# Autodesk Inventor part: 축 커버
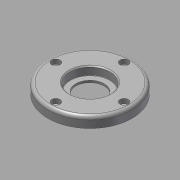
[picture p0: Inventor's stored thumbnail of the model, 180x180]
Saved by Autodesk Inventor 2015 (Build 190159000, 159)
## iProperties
Created: 2015-10
Part Number: 축 커버
Document SubType Name: Modeling
Designer: mdu
Density: 1 g/cm^3
Material: 강철, 연강
Appearance: 강철
Author: mdu
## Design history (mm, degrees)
sketch "스케치1"
  geometry: C1 r 40 at (0, 0) reference; C2 r 26 at (0, 0) reference; 1 further point
  node "참조1"
  node "참조2"
extrude "돌출1" new body sketch "스케치1" distance "d0" = 10; taper "d1" = 0 deg
extrude "돌출2" join sketch "스케치1" distance "d2" = 3; taper "d3" = 0 deg
hole "구멍1" diameter "d6" = 27; stored, may be unused: countersink angle "d10" = 90 deg, drill point angle "d12" = 118 deg; dims "d4" = 10, "d5" = 10, "d7" = 6, "d8" = 38, "d9" = 8, "d11" = 8
sketch "스케치2"
  geometry: C1 r 20 at (0, 0); 1 further point
  constraints: 1 centre point, 1 coincident
  dimensions: "d13" = 40 diameter of C1
extrude "돌출3" cut sketch "스케치2" distance "d14" = 3; taper "d15" = 0 deg
sketch "스케치3"
  geometry: C1 r 1.621 at (0, 32.5) reference; 1 further point
hole "구멍2" sketch "스케치3" at (0, 32.5) diameter "d16" = 4.5; stored, may be unused: countersink angle "d20" = 90 deg, drill point angle "d22" = 118 deg; dims "d17" = 6, "d18" = 8, "d19" = 4.4, "d21" = 8
fillet "모깎기1" dims "d26" = 3, "d27" = 0.3
chamfer "모따기1" distance "d28" = 1; stored, may be unused: second distance "d29" = 2, angle "d30" = 45 deg
node "솔리드1"
pattern_circular "원형 패턴1" dims angle "d24" = 360 deg
node "참조3"
